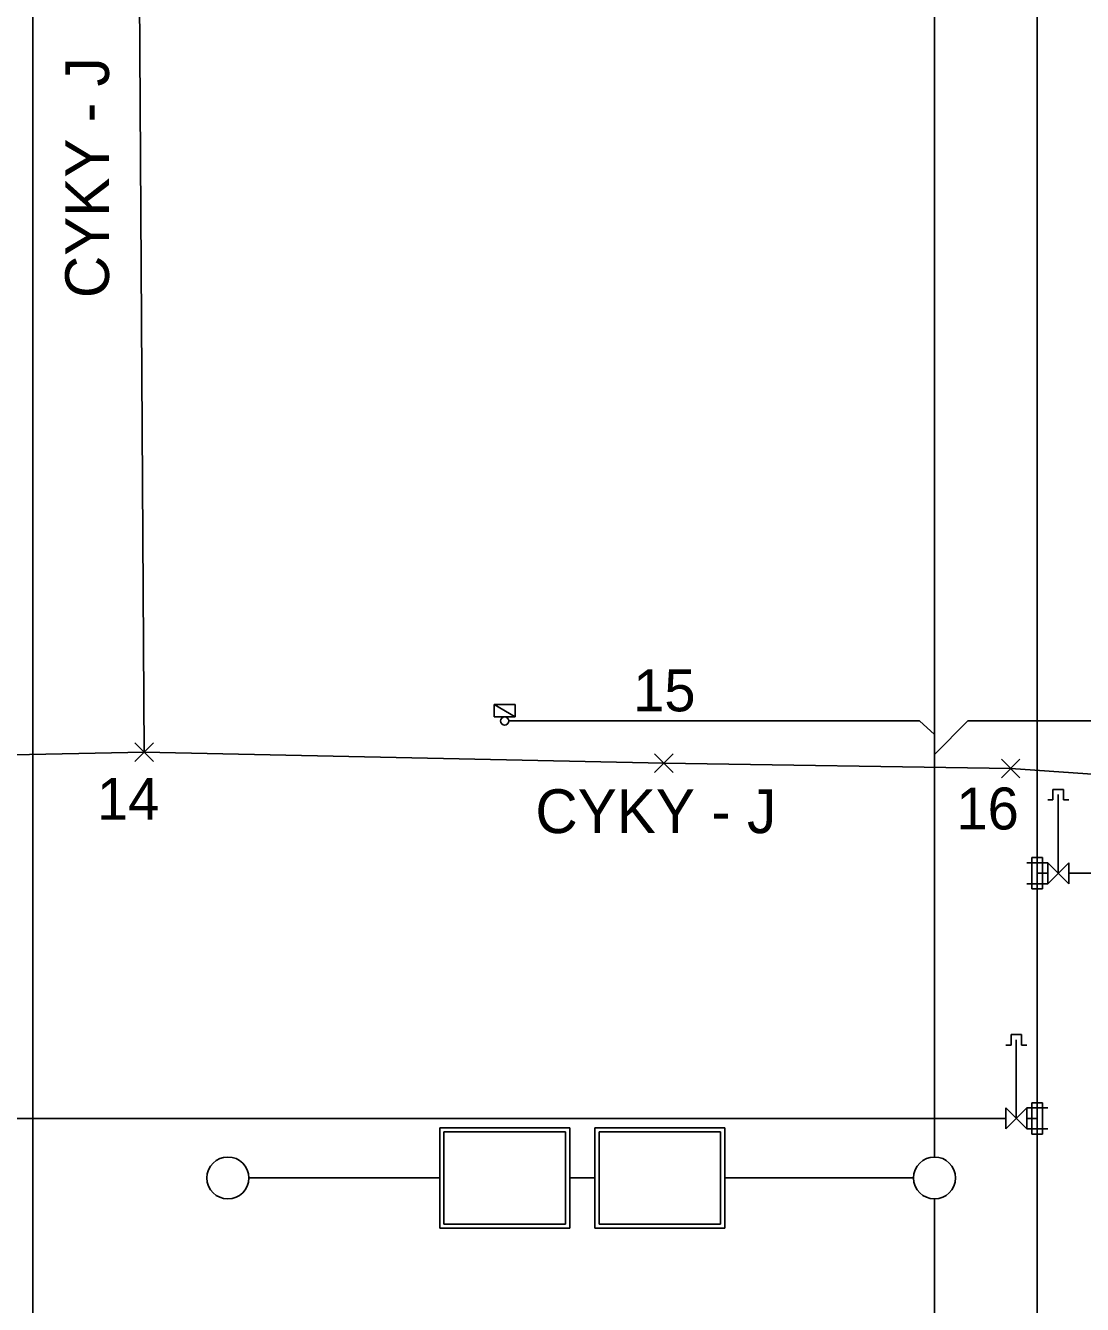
# Model space of a CAD drawing. Extents: x -263993 to -263783, y -1242294 to -1242146.
# Drawn here: x -263948.27 to -263923.07, y -1242207.77 to -1242177.26 of the extents above; entities that cross this region are included whole.
import ezdxf

# ---------------------------------------------------------------- set-up
doc = ezdxf.new("R2010")
doc.units = 0
for name, color, linetype in [('KFA_2D_SITUACIA_DSP', 7, 'Continuous'), ('KFA_ROZVODY_NN_BODY', 7, 'Continuous'), ('KFA_ROZVODY_NN_TRASA', 7, 'Continuous'), ('POPIS', 7, 'Continuous')]:
    doc.layers.add(name, color=color, linetype=linetype)

msp = doc.modelspace()

# ---------------------------------------------------------------- linework, layer by layer
at = {"layer": 'KFA_2D_SITUACIA_DSP'}
for p, q in [((-263948.093, -1242145.754), (-263948.093, -1242241.458)), ((-263924.143, -1242145.754), (-263924.143, -1242185.14)), ((-263926.593, -1242155.252), (-263926.593, -1242204.252)), ((-263924.143, -1242185.14), (-263924.143, -1242250.14)), ((-263937.093, -1242193.752), (-263937.093, -1242193.462)), ((-263937.093, -1242193.462), (-263936.593, -1242193.462)), ((-263936.593, -1242193.752), (-263937.093, -1242193.462)), ((-263936.593, -1242193.752), (-263937.093, -1242193.462)), ((-263937.093, -1242193.462), (-263937.093, -1242193.752)), ((-263936.593, -1242193.752), (-263937.093, -1242193.752)), ((-263937.093, -1242193.752), (-263936.593, -1242193.752)), ((-263936.593, -1242193.462), (-263936.593, -1242193.752)), ((-263936.743, -1242193.852), (-263926.953, -1242193.852)), ((-263926.953, -1242193.852), (-263926.593, -1242194.178)), ((-263925.798, -1242193.852), (-263926.593, -1242194.648)), ((-263920.944, -1242193.852), (-263925.798, -1242193.852)), ((-263923.768, -1242195.732), (-263923.768, -1242195.482)), ((-263923.768, -1242195.482), (-263923.518, -1242195.482)), ((-263923.518, -1242195.482), (-263923.518, -1242195.732)), ((-263923.768, -1242195.732), (-263923.893, -1242195.732)), ((-263923.643, -1242197.482), (-263923.643, -1242195.607)), ((-263923.518, -1242195.732), (-263923.393, -1242195.732)), ((-263924.018, -1242197.107), (-263924.268, -1242197.107)), ((-263924.268, -1242197.107), (-263924.268, -1242197.857)), ((-263924.018, -1242197.857), (-263924.018, -1242197.107)), ((-263923.893, -1242197.232), (-263924.393, -1242197.232)), ((-263923.893, -1242197.732), (-263923.893, -1242197.232)), ((-263923.893, -1242197.232), (-263923.393, -1242197.732)), ((-263923.393, -1242197.232), (-263923.893, -1242197.732)), ((-263923.393, -1242197.732), (-263923.393, -1242197.232)), ((-263924.143, -1242197.482), (-263923.893, -1242197.482)), ((-263923.893, -1242197.482), (-263924.143, -1242197.482)), ((-263923.393, -1242197.482), (-263915.293, -1242197.482)), ((-263923.893, -1242197.732), (-263924.393, -1242197.732)), ((-263924.268, -1242197.857), (-263924.018, -1242197.857)), ((-263924.768, -1242201.332), (-263924.768, -1242201.582)), ((-263924.518, -1242201.332), (-263924.768, -1242201.332)), ((-263924.518, -1242201.582), (-263924.518, -1242201.332)), ((-263924.768, -1242201.582), (-263924.893, -1242201.582)), ((-263924.643, -1242203.332), (-263924.643, -1242201.457)), ((-263924.518, -1242201.582), (-263924.393, -1242201.582)), ((-263924.893, -1242203.582), (-263924.893, -1242203.082)), ((-263924.393, -1242203.082), (-263924.893, -1242203.582)), ((-263924.893, -1242203.082), (-263924.393, -1242203.582)), ((-263924.393, -1242203.582), (-263924.393, -1242203.082)), ((-263924.393, -1242203.082), (-263923.893, -1242203.082)), ((-263924.268, -1242203.707), (-263924.268, -1242202.957)), ((-263924.268, -1242202.957), (-263924.018, -1242202.957)), ((-263924.018, -1242202.957), (-263924.018, -1242203.707)), ((-263924.893, -1242203.332), (-263958.097, -1242203.332)), ((-263924.143, -1242203.332), (-263924.393, -1242203.332)), ((-263924.393, -1242203.332), (-263924.143, -1242203.332)), ((-263938.393, -1242203.552), (-263935.293, -1242203.552)), ((-263938.393, -1242205.952), (-263938.393, -1242203.552)), ((-263938.293, -1242205.852), (-263938.293, -1242203.652)), ((-263938.293, -1242203.652), (-263935.393, -1242203.652)), ((-263935.393, -1242205.852), (-263935.393, -1242203.652)), ((-263935.293, -1242205.952), (-263935.293, -1242203.552)), ((-263934.693, -1242203.552), (-263931.593, -1242203.552)), ((-263934.693, -1242203.552), (-263934.693, -1242205.952)), ((-263934.593, -1242203.652), (-263934.593, -1242205.852)), ((-263934.593, -1242203.652), (-263931.693, -1242203.652)), ((-263931.693, -1242203.652), (-263931.693, -1242205.852)), ((-263931.593, -1242203.552), (-263931.593, -1242205.952)), ((-263924.393, -1242203.582), (-263923.893, -1242203.582)), ((-263924.018, -1242203.707), (-263924.268, -1242203.707)), ((-263938.393, -1242204.752), (-263942.945, -1242204.752)), ((-263934.693, -1242204.752), (-263935.293, -1242204.752)), ((-263927.093, -1242204.752), (-263931.593, -1242204.752)), ((-263926.593, -1242221.011), (-263926.593, -1242205.252)), ((-263935.293, -1242205.952), (-263938.393, -1242205.952)), ((-263935.393, -1242205.852), (-263938.293, -1242205.852)), ((-263931.593, -1242205.952), (-263934.693, -1242205.952)), ((-263931.693, -1242205.852), (-263934.593, -1242205.852))]:
    msp.add_line(p, q, dxfattribs=at)
for centre, radius in [((-263936.843, -1242193.852), 0.1), ((-263943.445, -1242204.752), 0.5), ((-263926.593, -1242204.752), 0.5)]:
    msp.add_circle(centre, radius, dxfattribs=at)
at = {"layer": 'KFA_ROZVODY_NN_BODY'}
for p, q in [((-263945.664, -1242194.815), (-263945.222, -1242194.373)), ((-263945.222, -1242194.815), (-263945.664, -1242194.373)), ((-263933.267, -1242195.081), (-263932.825, -1242194.639)), ((-263932.825, -1242195.081), (-263933.267, -1242194.639)), ((-263924.997, -1242195.205), (-263924.555, -1242194.763)), ((-263924.555, -1242195.205), (-263924.997, -1242194.763))]:
    msp.add_line(p, q, dxfattribs=at)
at = {"layer": 'KFA_ROZVODY_NN_TRASA'}
for p, q in [((-263945.606, -1242168.14), (-263945.443, -1242194.594)), ((-263945.443, -1242194.594), (-263951.847, -1242194.729)), ((-263945.443, -1242194.594), (-263933.046, -1242194.86)), ((-263933.046, -1242194.86), (-263924.776, -1242194.984)), ((-263924.776, -1242194.984), (-263919.939, -1242195.319))]:
    msp.add_line(p, q, dxfattribs=at)

# ---------------------------------------------------------------- texts
at = {"layer": 'KFA_ROZVODY_NN_BODY'}
for s, p in [('15', (-263933.78, -1242193.622)), ('14', (-263946.566, -1242196.208)), ('16', (-263926.07, -1242196.439))]:
    msp.add_text(s, height=1, dxfattribs=at).set_placement(p)
at = {"layer": 'POPIS'}
msp.add_text('CYKY - J', height=1.045, rotation=90, dxfattribs=at).set_placement((-263946.279, -1242183.765))
msp.add_text('CYKY - J', height=1.045, dxfattribs=at).set_placement((-263936.111, -1242196.526))

doc.saveas('drawing.dxf')
